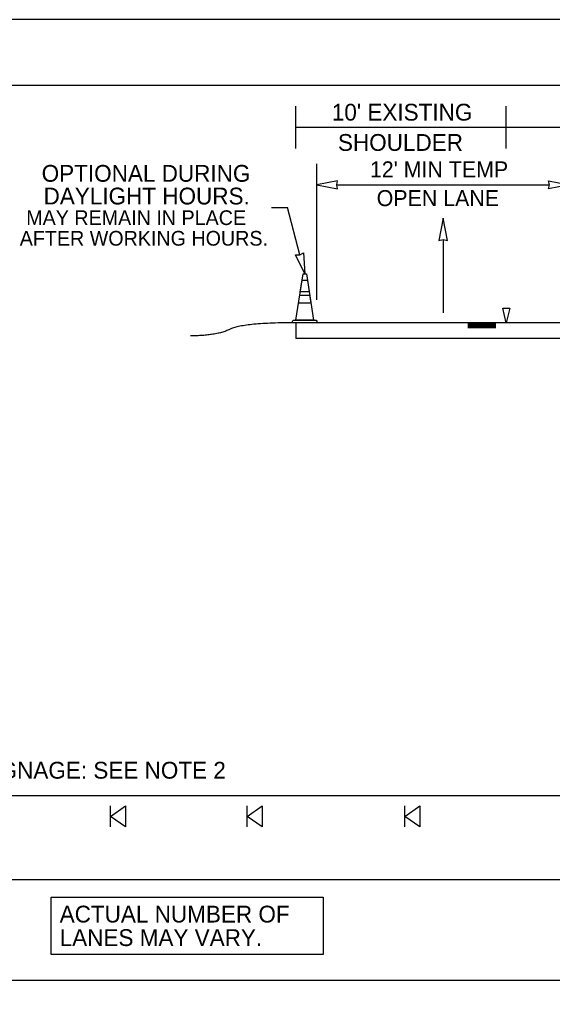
# Model space of a CAD drawing. Extents: x 99999 to 100116, y 99995 to 100013.
# Drawn here: x 100004.144 to 100006.677, y 100006.016 to 100010.687 of the extents above; entities that cross this region are included whole.
import ezdxf

# ---------------------------------------------------------------- set-up
doc = ezdxf.new("R2010")
doc.units = 0
for name, color, linetype in [('RD_ED_ShoulderPavedEdge', 7, 'Continuous'), ('RD_MK_LineEdgeYellow', 7, 'Continuous'), ('RD_MK_LineLane', 7, 'Continuous'), ('SH_GI_PlotLimits', 7, 'Continuous'), ('SH_GI_SheetBorder', 7, 'Continuous'), ('SH_TI_Tables', 7, 'Continuous'), ('SH_TI_WZSectionCut', 7, 'Continuous'), ('TR_WZ_ArrowLeftStrRightTurn', 7, 'Continuous'), ('TR_WZ_PortableSignMountBlk-Org', 7, 'Continuous'), ('TR_WZ_PortableSignMountBlk-Wht', 7, 'Continuous'), ('TR_WZ_TrafficConeElev', 7, 'Continuous'), ('TR_WZ_WorkZoneDetails', 7, 'Continuous'), ('TR_WZ_WorkZoneTextCurrent', 7, 'Continuous')]:
    doc.layers.add(name, color=color, linetype=linetype)

msp = doc.modelspace()

# ---------------------------------------------------------------- linework, layer by layer
at = {"layer": 'RD_ED_ShoulderPavedEdge'}
msp.add_line((100000.8283, 100006.9957), (100015.62, 100006.9957), dxfattribs=at)
at = {"layer": 'RD_MK_LineEdgeYellow'}
msp.add_line((100000.8283, 100006.5957), (100015.62, 100006.5957), dxfattribs=at)
at = {"layer": 'RD_MK_LineLane'}
msp.add_lwpolyline([(100015.62, 100006.1157), (100000.8283, 100006.1157)], dxfattribs=at)
at = {"layer": 'SH_GI_PlotLimits'}
msp.add_lwpolyline([(99999.0625, 99999.6875), (100016.0625, 99999.6875), (100016.0625, 100010.6875), (99999.0625, 100010.6875)], close=True, dxfattribs=at)
at = {"layer": 'SH_GI_SheetBorder'}
msp.add_line((100000, 100010.375), (100015.75, 100010.375), dxfattribs=at)
at = {"layer": 'SH_TI_Tables'}
msp.add_lwpolyline([(100004.2941, 100006.511), (100005.5872, 100006.511), (100005.5872, 100006.239), (100004.2941, 100006.239)], close=True, dxfattribs=at)
at = {"layer": 'SH_TI_WZSectionCut'}
for p, q in [((100005.4578, 100010.075), (100005.4578, 100010.275)), ((100006.4578, 100010.075), (100006.4578, 100010.275)), ((100005.4578, 100010.175), (100006.4578, 100010.175)), ((100006.4578, 100010.175), (100007.6578, 100010.175)), ((100005.5578, 100009.3547), (100005.5578, 100010.001)), ((100005.6515, 100009.901), (100006.664, 100009.901)), ((100005.4578, 100009.2449), (100005.4578, 100009.1699)), ((100009.8578, 100009.2449), (100005.4578, 100009.2449)), ((100006.2748, 100009.2397), (100006.4078, 100009.2397)), ((100006.2748, 100009.2341), (100006.4078, 100009.2341)), ((100006.2748, 100009.2284), (100006.4078, 100009.2284)), ((100006.2748, 100009.2232), (100006.4078, 100009.2232)), ((100009.8578, 100009.1699), (100005.4578, 100009.1699))]:
    msp.add_line(p, q, dxfattribs=at)
for points in [[(100005.5578, 100009.901), (100005.656, 100009.8817), (100005.6515, 100009.901), (100005.656, 100009.9203)], [(100006.7578, 100009.901), (100006.6595, 100009.8817), (100006.664, 100009.901), (100006.6595, 100009.9203)], [(100006.4411, 100009.3147), (100006.4744, 100009.3147), (100006.4578, 100009.2449)]]:
    msp.add_lwpolyline(points, close=True, dxfattribs=at)
msp.add_open_spline([(100005.4578, 100009.2449), (100005.2066, 100009.2449), (100005.0811, 100009.1828), (100004.9556, 100009.1828)], degree=2, dxfattribs=at)
at = {"layer": 'TR_WZ_ArrowLeftStrRightTurn'}
msp.add_line((100006.1578, 100009.6418), (100006.1578, 100009.292), dxfattribs=at)
msp.add_lwpolyline([(100006.1578, 100009.742), (100006.1372, 100009.6369), (100006.1578, 100009.6418), (100006.1784, 100009.6369)], close=True, dxfattribs=at)
at = {"layer": 'TR_WZ_PortableSignMountBlk-Org'}
for p, q in [((100004.5753, 100006.8458), (100004.5753, 100006.9458)), ((100005.9753, 100006.8458), (100005.9753, 100006.9458))]:
    msp.add_line(p, q, dxfattribs=at)
for points in [[(100004.5753, 100006.8957), (100004.6471, 100006.9458), (100004.6471, 100006.8458)], [(100005.9753, 100006.8957), (100006.0471, 100006.9458), (100006.0471, 100006.8458)]]:
    msp.add_lwpolyline(points, close=True, dxfattribs=at)
at = {"layer": 'TR_WZ_PortableSignMountBlk-Wht'}
msp.add_line((100005.2253, 100006.8457), (100005.2253, 100006.9457), dxfattribs=at)
msp.add_lwpolyline([(100005.2253, 100006.8956), (100005.2971, 100006.9457), (100005.2971, 100006.8457)], close=True, dxfattribs=at)
at = {"layer": 'TR_WZ_TrafficConeElev'}
for p, q in [((100005.4785, 100009.3929), (100005.4868, 100009.447)), ((100005.4868, 100009.447), (100005.512, 100009.447)), ((100005.512, 100009.447), (100005.5203, 100009.3929)), ((100005.5203, 100009.3929), (100005.4785, 100009.3929)), ((100005.4702, 100009.3387), (100005.476, 100009.3762)), ((100005.5286, 100009.3387), (100005.4702, 100009.3387)), ((100005.476, 100009.3762), (100005.5229, 100009.3762)), ((100005.5229, 100009.3762), (100005.5286, 100009.3387)), ((100005.4416, 100009.2533), (100005.4458, 100009.2574)), ((100005.4416, 100009.2449), (100005.4416, 100009.2533)), ((100005.5572, 100009.2449), (100005.4416, 100009.2449)), ((100005.5411, 100009.2574), (100005.5531, 100009.2574)), ((100005.5531, 100009.2574), (100005.5572, 100009.2533)), ((100005.5572, 100009.2533), (100005.5572, 100009.2449))]:
    msp.add_line(p, q, dxfattribs=at)
msp.add_lwpolyline([(100005.5411, 100009.2574), (100005.4578, 100009.2574), (100005.4916, 100009.4783), (100005.5072, 100009.4783)], close=True, dxfattribs=at)
msp.add_lwpolyline([(100005.5411, 100009.2574), (100005.4578, 100009.2574), (100005.4916, 100009.4783), (100005.5072, 100009.4783)], close=True, dxfattribs=at)
msp.add_lwpolyline([(100005.4458, 100009.2574), (100005.4578, 100009.2574), (100005.5411, 100009.2574)], dxfattribs=at)
at = {"layer": 'TR_WZ_WorkZoneDetails'}
for p in [(100005.3412, 100009.794), (100005.4758, 100009.569)]:
    msp.add_line(p, (100005.4175, 100009.794), dxfattribs=at)
msp.add_lwpolyline([(100005.4994, 100009.4783), (100005.4561, 100009.5686), (100005.4759, 100009.569), (100005.4934, 100009.5782)], close=True, dxfattribs=at)

# ---------------------------------------------------------------- texts
at = {"layer": 'SH_TI_Tables'}
for s, p in [('ACTUAL NUMBER OF', (100004.3341, 100006.391)), ('LANES MAY VARY.', (100004.3341, 100006.279))]:
    msp.add_text(s, height=0.08, rotation=360, dxfattribs=at).set_placement(p)
at = {"layer": 'SH_TI_WZSectionCut'}
for s, p in [("10' EXISTING", (100005.6283, 100010.207)), ('SHOULDER', (100005.6575, 100010.063))]:
    msp.add_text(s, height=0.08, rotation=360, dxfattribs=at).set_placement(p)
for s, p in [("12' MIN TEMP", (100005.8095, 100009.937)), ('OPEN LANE', (100005.8417, 100009.8002))]:
    msp.add_text(s, height=0.076, dxfattribs=at).set_placement(p)
at = {"layer": 'TR_WZ_WorkZoneTextCurrent'}
for s, height, p in [('OPTIONAL DURING', 0.08, (100004.2485, 100009.916)), ('DAYLIGHT HOURS.', 0.08, (100004.2575, 100009.808)), ('MAY REMAIN IN PLACE', 0.07, (100004.1751, 100009.71)), ('AFTER WORKING HOURS.', 0.07, (100004.1442, 100009.612)), ('LEFT SHOULDER SIGNAGE: SEE NOTE 2', 0.08, (100003.0319, 100007.0756))]:
    msp.add_text(s, height=height, dxfattribs=at).set_placement(p)

doc.saveas('drawing.dxf')
